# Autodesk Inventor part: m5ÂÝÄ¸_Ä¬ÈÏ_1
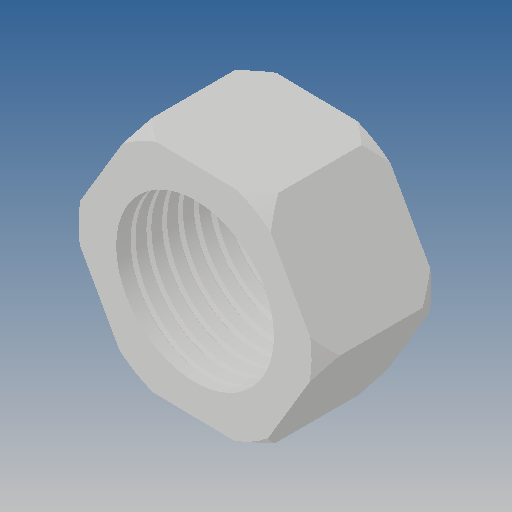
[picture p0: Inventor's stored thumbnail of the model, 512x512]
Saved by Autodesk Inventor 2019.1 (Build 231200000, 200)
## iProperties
Created: 2012-10
Part Number: m5ÂÝÄ¸_Ä¬ÈÏ_1
Material: Ogólny
Document SubType Name: Modeling
Designer: CADENGINEERING4
Density: 1 g/cm^3
Appearance: Domyślna
Author: CADENGINEERING4
Revision Number: ÈÎºÎ
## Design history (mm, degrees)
feature "NONE"
node "Bryła1"
